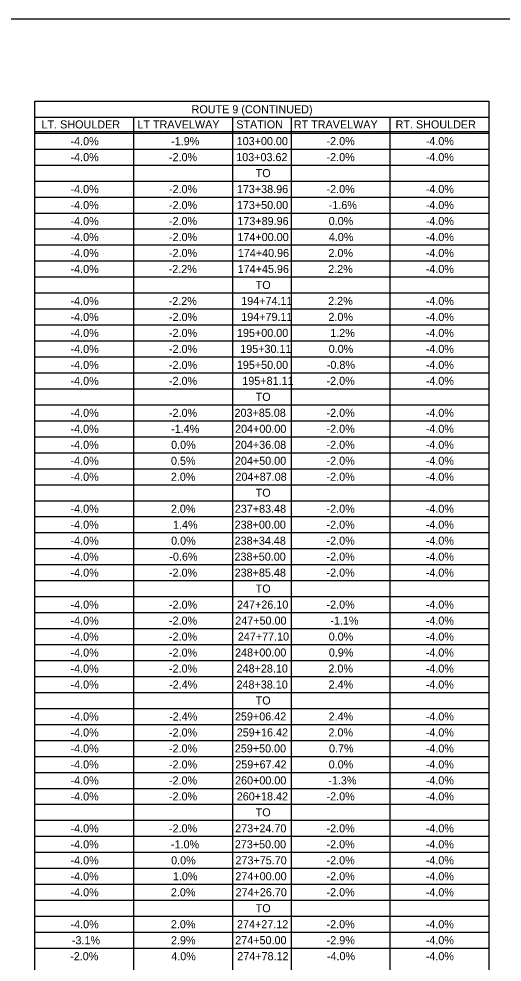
# Model space of a CAD drawing. Extents: x -15319374 to 1762012, y 465773 to 3693661.
# Drawn here: x -15314223.1 to -15314043.3, y 3693309.9 to 3693660.7 of the extents above; entities that cross this region are included whole.
import ezdxf

# ---------------------------------------------------------------- set-up
doc = ezdxf.new("R2010")
doc.units = 0
for name, color, linetype in [('BORDER', 7, 'Continuous'), ('Default', 7, 'Continuous'), ('DIMENSIONS', 7, 'Continuous')]:
    doc.layers.add(name, color=color, linetype=linetype)

msp = doc.modelspace()

# ---------------------------------------------------------------- linework, layer by layer
at = {"layer": 'BORDER'}
for p, q in [((-15314180.44, 3693624.08), (-15314180.44, 3693220.04)), ((-15314143.67, 3693624.08), (-15314143.67, 3693220.04)), ((-15314121.8, 3693624.08), (-15314121.8, 3693220.04)), ((-15314085.03, 3693624.08), (-15314085.03, 3693220.04)), ((-15314217.21, 3693618.8), (-15314048.26, 3693618.8)), ((-15314217.21, 3693618.2), (-15314048.26, 3693618.2)), ((-15314217.21, 3693612.26), (-15314048.26, 3693612.26)), ((-15314217.21, 3693612.26), (-15314048.26, 3693612.26)), ((-15314217.21, 3693612.26), (-15314048.26, 3693612.26)), ((-15314217.21, 3693606.32), (-15314048.26, 3693606.32)), ((-15314217.21, 3693600.38), (-15314048.26, 3693600.38)), ((-15314217.21, 3693594.43), (-15314048.26, 3693594.43)), ((-15314217.21, 3693588.49), (-15314048.26, 3693588.49)), ((-15314217.21, 3693582.55), (-15314048.26, 3693582.55)), ((-15314217.21, 3693576.6), (-15314048.26, 3693576.6)), ((-15314217.21, 3693570.66), (-15314048.26, 3693570.66)), ((-15314217.21, 3693564.72), (-15314048.26, 3693564.72)), ((-15314217.21, 3693558.78), (-15314048.26, 3693558.78)), ((-15314217.21, 3693552.83), (-15314048.26, 3693552.83)), ((-15314217.21, 3693546.89), (-15314048.26, 3693546.89)), ((-15314217.21, 3693540.95), (-15314048.26, 3693540.95)), ((-15314217.21, 3693535.01), (-15314048.26, 3693535.01)), ((-15314217.21, 3693529.06), (-15314048.26, 3693529.06)), ((-15314217.21, 3693523.12), (-15314048.26, 3693523.12)), ((-15314217.21, 3693517.18), (-15314048.26, 3693517.18)), ((-15314217.21, 3693511.24), (-15314048.26, 3693511.24)), ((-15314217.21, 3693505.29), (-15314048.26, 3693505.29)), ((-15314217.21, 3693499.35), (-15314048.26, 3693499.35)), ((-15314217.21, 3693493.41), (-15314048.26, 3693493.41)), ((-15314217.21, 3693487.46), (-15314048.26, 3693487.46)), ((-15314217.21, 3693481.52), (-15314048.26, 3693481.52)), ((-15314217.21, 3693475.58), (-15314048.26, 3693475.58)), ((-15314217.21, 3693469.64), (-15314048.26, 3693469.64)), ((-15314217.21, 3693463.69), (-15314048.26, 3693463.69)), ((-15314217.21, 3693457.75), (-15314048.26, 3693457.75)), ((-15314217.21, 3693451.81), (-15314048.26, 3693451.81)), ((-15314217.21, 3693445.87), (-15314048.26, 3693445.87)), ((-15314217.21, 3693439.92), (-15314048.26, 3693439.92)), ((-15314217.21, 3693433.98), (-15314048.26, 3693433.98)), ((-15314217.21, 3693428.04), (-15314048.26, 3693428.04)), ((-15314217.21, 3693422.09), (-15314048.26, 3693422.09)), ((-15314217.21, 3693416.15), (-15314048.26, 3693416.15)), ((-15314217.21, 3693410.21), (-15314048.26, 3693410.21)), ((-15314217.21, 3693404.27), (-15314048.26, 3693404.27)), ((-15314217.21, 3693398.32), (-15314048.26, 3693398.32)), ((-15314217.21, 3693392.38), (-15314048.26, 3693392.38)), ((-15314217.21, 3693386.44), (-15314048.26, 3693386.44)), ((-15314217.21, 3693380.5), (-15314048.26, 3693380.5)), ((-15314217.21, 3693374.55), (-15314048.26, 3693374.55)), ((-15314217.21, 3693368.61), (-15314048.26, 3693368.61)), ((-15314217.21, 3693362.67), (-15314048.26, 3693362.67)), ((-15314217.21, 3693356.72), (-15314048.26, 3693356.72)), ((-15314217.21, 3693350.78), (-15314048.26, 3693350.78)), ((-15314217.21, 3693344.84), (-15314048.26, 3693344.84)), ((-15314217.21, 3693338.9), (-15314048.26, 3693338.9)), ((-15314217.21, 3693332.95), (-15314048.26, 3693332.95)), ((-15314217.21, 3693327.01), (-15314048.26, 3693327.01)), ((-15314217.21, 3693321.07), (-15314048.26, 3693321.07)), ((-15314217.21, 3693315.13), (-15314048.26, 3693315.13))]:
    msp.add_line(p, q, dxfattribs=at)
msp.add_lwpolyline([(-15314217.21, 3693624.08), (-15314217.21, 3693630.02), (-15314048.26, 3693630.02), (-15314048.26, 3693624.08)], dxfattribs=at)
msp.add_lwpolyline([(-15314217.21, 3693624.08), (-15314048.26, 3693624.08), (-15314048.26, 3693220.04), (-15314217.21, 3693220.04)], close=True, dxfattribs=at)
at = {"layer": 'Default'}
msp.add_lwpolyline([(-15314452.76, 3693660.68), (-15313582.2, 3693660.68), (-15313582.2, 3693071.2), (-15314452.76, 3693071.2)], close=True, dxfattribs=at)

# ---------------------------------------------------------------- texts
at = {"layer": 'DIMENSIONS'}
for s, p in [('ROUTE 9 (CONTINUED)', (-15314158.83, 3693625.55)), ('LT. SHOULDER', (-15314214.66, 3693619.94)), ('LT TRAVELWAY', (-15314178.99, 3693619.94)), ('STATION', (-15314142.21, 3693619.94)), ('RT TRAVELWAY', (-15314120.78, 3693619.94)), ('RT. SHOULDER', (-15314082.91, 3693619.94)), ('-4.0%', (-15314203.88, 3693613.7)), ('-1.9%', (-15314166.45, 3693613.7)), ('103+00.00', (-15314142.06, 3693613.72)), ('-2.0%', (-15314108.61, 3693613.72)), ('-4.0%', (-15314071.7, 3693613.72)), ('-4.0%', (-15314203.88, 3693607.76)), ('-2.0%', (-15314167.25, 3693607.76)), ('103+03.62', (-15314142.22, 3693607.77)), ('-2.0%', (-15314108.61, 3693607.77)), ('-4.0%', (-15314071.7, 3693607.77)), ('TO', (-15314134.98, 3693601.83)), ('-4.0%', (-15314203.88, 3693595.87)), ('-2.0%', (-15314167.25, 3693595.87)), ('173+38.96', (-15314141.97, 3693595.89)), ('-2.0%', (-15314108.61, 3693595.89)), ('-4.0%', (-15314071.7, 3693595.89)), ('-4.0%', (-15314203.88, 3693589.93)), ('-2.0%', (-15314167.25, 3693589.93)), ('173+50.00', (-15314141.99, 3693589.95)), ('-1.6%', (-15314107.81, 3693589.95)), ('-4.0%', (-15314071.7, 3693589.95)), ('-4.0%', (-15314203.88, 3693583.99)), ('-2.0%', (-15314167.25, 3693583.99)), ('173+89.96', (-15314141.8, 3693584)), ('0.0%', (-15314107.81, 3693584)), ('-4.0%', (-15314071.7, 3693584)), ('-4.0%', (-15314203.88, 3693578.04)), ('-2.0%', (-15314167.25, 3693578.04)), ('174+00.00', (-15314141.78, 3693578.06)), ('4.0%', (-15314107.76, 3693578.06)), ('-4.0%', (-15314071.7, 3693578.06)), ('-4.0%', (-15314203.88, 3693572.1)), ('-2.0%', (-15314167.25, 3693572.1)), ('174+40.96', (-15314141.64, 3693572.12)), ('2.0%', (-15314107.9, 3693572.12)), ('-4.0%', (-15314071.7, 3693572.12)), ('-4.0%', (-15314203.88, 3693566.16)), ('-2.2%', (-15314167.35, 3693566.16)), ('174+45.96', (-15314141.68, 3693566.17)), ('2.2%', (-15314108, 3693566.17)), ('-4.0%', (-15314071.7, 3693566.17)), ('TO', (-15314134.98, 3693560.23)), ('-4.0%', (-15314203.88, 3693554.27)), ('-2.2%', (-15314167.35, 3693554.27)), ('194+74.11', (-15314140.36, 3693554.29)), ('2.2%', (-15314108, 3693554.29)), ('-4.0%', (-15314071.7, 3693554.29)), ('-4.0%', (-15314203.88, 3693548.33)), ('-2.0%', (-15314167.25, 3693548.33)), ('194+79.11', (-15314140.36, 3693548.35)), ('2.0%', (-15314107.9, 3693548.35)), ('-4.0%', (-15314071.7, 3693548.35)), ('-4.0%', (-15314203.88, 3693542.39)), ('-2.0%', (-15314167.25, 3693542.39)), ('195+00.00', (-15314141.94, 3693542.4)), ('1.2%', (-15314107.24, 3693542.4)), ('-4.0%', (-15314071.7, 3693542.4)), ('-4.0%', (-15314203.88, 3693536.44)), ('-2.0%', (-15314167.25, 3693536.44)), ('195+30.11', (-15314140.74, 3693536.46)), ('0.0%', (-15314107.81, 3693536.46)), ('-4.0%', (-15314071.7, 3693536.46)), ('-4.0%', (-15314203.88, 3693530.5)), ('-2.0%', (-15314167.25, 3693530.5)), ('195+50.00', (-15314141.99, 3693530.52)), ('-0.8%', (-15314108.51, 3693530.52)), ('-4.0%', (-15314071.7, 3693530.52)), ('-4.0%', (-15314203.88, 3693524.56)), ('-2.0%', (-15314167.25, 3693524.56)), ('195+81.11', (-15314139.96, 3693524.58)), ('-2.0%', (-15314108.61, 3693524.58)), ('-4.0%', (-15314071.7, 3693524.58)), ('TO', (-15314134.98, 3693518.63)), ('-4.0%', (-15314203.88, 3693512.67)), ('-2.0%', (-15314167.25, 3693512.67)), ('203+85.08', (-15314142.85, 3693512.69)), ('-2.0%', (-15314108.61, 3693512.69)), ('-4.0%', (-15314071.7, 3693512.69)), ('-4.0%', (-15314203.88, 3693506.73)), ('-1.4%', (-15314166.45, 3693506.73)), ('204+00.00', (-15314142.65, 3693506.75)), ('-2.0%', (-15314108.61, 3693506.75)), ('-4.0%', (-15314071.7, 3693506.75)), ('-4.0%', (-15314203.88, 3693500.79)), ('0.0%', (-15314166.45, 3693500.79)), ('204+36.08', (-15314142.71, 3693500.8)), ('-2.0%', (-15314108.61, 3693500.8)), ('-4.0%', (-15314071.7, 3693500.8)), ('-4.0%', (-15314203.88, 3693494.85)), ('0.5%', (-15314166.5, 3693494.85)), ('204+50.00', (-15314142.7, 3693494.86)), ('-2.0%', (-15314108.61, 3693494.86)), ('-4.0%', (-15314071.7, 3693494.86)), ('-4.0%', (-15314203.88, 3693488.9)), ('2.0%', (-15314166.54, 3693488.9)), ('204+87.08', (-15314142.52, 3693488.92)), ('-2.0%', (-15314108.61, 3693488.92)), ('-4.0%', (-15314071.7, 3693488.92)), ('TO', (-15314134.98, 3693482.98)), ('-4.0%', (-15314203.88, 3693477.02)), ('2.0%', (-15314166.54, 3693477.02)), ('237+83.48', (-15314142.76, 3693477.03)), ('-2.0%', (-15314108.61, 3693477.03)), ('-4.0%', (-15314071.7, 3693477.03)), ('-4.0%', (-15314203.88, 3693471.07)), ('1.4%', (-15314165.74, 3693471.07)), ('238+00.00', (-15314142.82, 3693471.09)), ('-2.0%', (-15314108.61, 3693471.09)), ('-4.0%', (-15314071.7, 3693471.09)), ('-4.0%', (-15314203.88, 3693465.13)), ('0.0%', (-15314166.45, 3693465.13)), ('238+34.48', (-15314142.83, 3693465.15)), ('-2.0%', (-15314108.61, 3693465.15)), ('-4.0%', (-15314071.7, 3693465.15)), ('-4.0%', (-15314203.88, 3693459.19)), ('-0.6%', (-15314167.11, 3693459.19)), ('238+50.00', (-15314142.87, 3693459.21)), ('-2.0%', (-15314108.61, 3693459.21)), ('-4.0%', (-15314071.7, 3693459.21)), ('-4.0%', (-15314203.88, 3693453.25)), ('-2.0%', (-15314167.25, 3693453.25)), ('238+85.48', (-15314142.81, 3693453.26)), ('-2.0%', (-15314108.61, 3693453.26)), ('-4.0%', (-15314071.7, 3693453.26)), ('TO', (-15314134.98, 3693447.32)), ('-4.0%', (-15314203.88, 3693441.36)), ('-2.0%', (-15314167.25, 3693441.36)), ('247+26.10', (-15314141.92, 3693441.38)), ('-2.0%', (-15314108.61, 3693441.38)), ('-4.0%', (-15314071.7, 3693441.38)), ('-4.0%', (-15314203.88, 3693435.42)), ('-2.0%', (-15314167.25, 3693435.42)), ('247+50.00', (-15314142.58, 3693435.43)), ('-1.1%', (-15314107.19, 3693435.43)), ('-4.0%', (-15314071.7, 3693435.43)), ('-4.0%', (-15314203.88, 3693429.48)), ('-2.0%', (-15314167.25, 3693429.48)), ('247+77.10', (-15314141.64, 3693429.49)), ('0.0%', (-15314107.81, 3693429.49)), ('-4.0%', (-15314071.7, 3693429.49)), ('-4.0%', (-15314203.88, 3693423.53)), ('-2.0%', (-15314167.25, 3693423.53)), ('248+00.00', (-15314142.65, 3693423.55)), ('0.9%', (-15314107.76, 3693423.55)), ('-4.0%', (-15314071.7, 3693423.55)), ('-4.0%', (-15314203.88, 3693417.59)), ('-2.0%', (-15314167.25, 3693417.59)), ('248+28.10', (-15314142.09, 3693417.61)), ('2.0%', (-15314107.9, 3693417.61)), ('-4.0%', (-15314071.7, 3693417.61)), ('-4.0%', (-15314203.88, 3693411.65)), ('-2.4%', (-15314167.2, 3693411.65)), ('248+38.10', (-15314142.11, 3693411.66)), ('2.4%', (-15314107.85, 3693411.66)), ('-4.0%', (-15314071.7, 3693411.66)), ('TO', (-15314134.98, 3693405.72)), ('-4.0%', (-15314203.88, 3693399.76)), ('-2.4%', (-15314167.2, 3693399.76)), ('259+06.42', (-15314142.69, 3693399.78)), ('2.4%', (-15314107.85, 3693399.78)), ('-4.0%', (-15314071.7, 3693399.78)), ('-4.0%', (-15314203.88, 3693393.82)), ('-2.0%', (-15314167.25, 3693393.82)), ('259+16.42', (-15314142.03, 3693393.84)), ('2.0%', (-15314107.9, 3693393.84)), ('-4.0%', (-15314071.7, 3693393.84)), ('-4.0%', (-15314203.88, 3693387.88)), ('-2.0%', (-15314167.25, 3693387.88)), ('259+50.00', (-15314142.75, 3693387.89)), ('0.7%', (-15314107.69, 3693387.89)), ('-4.0%', (-15314071.7, 3693387.89)), ('-4.0%', (-15314203.88, 3693381.93)), ('-2.0%', (-15314167.25, 3693381.93)), ('259+67.42', (-15314142.57, 3693381.95)), ('0.0%', (-15314107.81, 3693381.95)), ('-4.0%', (-15314071.7, 3693381.95)), ('-4.0%', (-15314203.88, 3693375.99)), ('-2.0%', (-15314167.25, 3693375.99)), ('260+00.00', (-15314142.65, 3693376.01)), ('-1.3%', (-15314107.97, 3693376.01)), ('-4.0%', (-15314071.7, 3693376.01)), ('-4.0%', (-15314203.88, 3693370.05)), ('-2.0%', (-15314167.25, 3693370.05)), ('260+18.42', (-15314142.03, 3693370.06)), ('-2.0%', (-15314108.61, 3693370.06)), ('-4.0%', (-15314071.7, 3693370.06)), ('TO', (-15314134.98, 3693364.12)), ('-4.0%', (-15314203.88, 3693358.16)), ('-2.0%', (-15314167.25, 3693358.16)), ('273+24.70', (-15314142.63, 3693358.18)), ('-2.0%', (-15314108.61, 3693358.18)), ('-4.0%', (-15314071.7, 3693358.18)), ('-4.0%', (-15314203.88, 3693352.22)), ('-1.0%', (-15314166.5, 3693352.22)), ('273+50.00', (-15314142.75, 3693352.24)), ('-2.0%', (-15314108.61, 3693352.24)), ('-4.0%', (-15314071.7, 3693352.24)), ('-4.0%', (-15314203.88, 3693346.28)), ('0.0%', (-15314166.45, 3693346.28)), ('273+75.70', (-15314142.51, 3693346.29)), ('-2.0%', (-15314108.61, 3693346.29)), ('-4.0%', (-15314071.7, 3693346.29)), ('-4.0%', (-15314203.88, 3693340.33)), ('1.0%', (-15314165.79, 3693340.33)), ('274+00.00', (-15314142.54, 3693340.35)), ('-2.0%', (-15314108.61, 3693340.35)), ('-4.0%', (-15314071.7, 3693340.35)), ('-4.0%', (-15314203.88, 3693334.39)), ('2.0%', (-15314166.54, 3693334.39)), ('274+26.70', (-15314142.46, 3693334.41)), ('-2.0%', (-15314108.61, 3693334.41)), ('-4.0%', (-15314071.7, 3693334.41)), ('TO', (-15314134.98, 3693328.47)), ('-4.0%', (-15314203.88, 3693322.51)), ('2.0%', (-15314166.54, 3693322.51)), ('274+27.12', (-15314141.93, 3693322.52)), ('-2.0%', (-15314108.61, 3693322.52)), ('-4.0%', (-15314071.7, 3693322.52)), ('-3.1%', (-15314203.38, 3693316.56)), ('2.9%', (-15314166.5, 3693316.56)), ('274+50.00', (-15314142.58, 3693316.58)), ('-2.9%', (-15314108.56, 3693316.58)), ('-4.0%', (-15314071.7, 3693316.58)), ('-2.0%', (-15314204.02, 3693310.62)), ('4.0%', (-15314166.4, 3693310.62)), ('274+78.12', (-15314141.84, 3693310.64)), ('-4.0%', (-15314108.47, 3693310.64)), ('-4.0%', (-15314071.7, 3693310.64))]:
    msp.add_text(s, height=3, dxfattribs=at).set_placement(p)

doc.saveas('drawing.dxf')
